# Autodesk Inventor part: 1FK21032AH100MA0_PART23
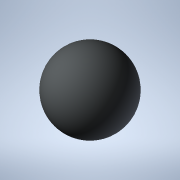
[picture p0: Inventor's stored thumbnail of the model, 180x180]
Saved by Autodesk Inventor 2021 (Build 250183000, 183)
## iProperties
Created: 2025-04
Part Number: 1FK21032AH100MA0_PART23
Material: Generic
Catalog Web Link: www.3dfindit.com
Description: -Servo synchronous motor
Document SubType Name: Modeling
Designer: psAdmin
Mass: 0.113097 g
Surface Area: 1.13097 cm^2
Volume: 0.113097 cm^3
Density: 1 g/cm^3
Appearance: PSOLRGB-212-217-219
Category: PARTsolutions
Title: 1FK21032AH100MA0_PART23
Author: Cadenas PARTsolutions
Comments: Servo synchronous motor
Sending System: PARTsolutions
Preprocessor: ST-DEVELOPER v19.3
PSOL_IDENT_0: {$CADENAS_DATA/23d-libs/siemens_ag/_cat_/12/33/1fk21032ah100ma0.prj},216 {VTYP=3D},{NB=1FK21032AH100
PSOL_IDENT_1: MA0_PART23},{LINA=1FK21032AH100MA0_PART23},{NN=1FK21032AH100MA0_PART23},{NOPRJ=TRUE},{DATE=19.08.202
PSOL_IDENT_2: 5 14:00:27},{GEOMDATE=30.07.2025 02:02:58},{VERSION=},{LINEID=10},{WBVAR=},{WBNUMERIC=}  {NB=1FK2103
PSOL_IDENT_3: 2AH100MA0_PART23},{LINA=1FK21032AH100MA0_PART23},{KT=DUMMY},{PREVIEW=../../../_pool_/d3/78/p_d211_xx
PSOL_IDENT_4: _00934j.png},{DESCSHORT=SIMOTICS S-1FK2 HD, SINAMICS S210 3AC 400V-480V, 0.59 Nm, 4500 rpm},{DESCLON
PSOL_IDENT_5: G=SIMOTICS S-1FK2 HD servo motor M0=0.64 Nm; PN = 0.28 kW at nN=4500 rpm (380-480 V); PN = 0.167 kW
PSOL_IDENT_6: at nN=2500 rpm (200-240 V); with holding brake; degree of protection IP64; cylindrical shaft D14 x 3
PSOL_IDENT_7: 0 mm; absolute encoder 22-bit + 12-bit multiturn (encoder AM22DQC); with OCC interface; plug size M1
PSOL_IDENT_8: 7, rotatable; SIMOTICS S-1FK2 servomotorfor a wide range of uses in industrial environments. SIMOTIC
PSOL_IDENT_9: S S‑1FK2 servomotors are compact synchronous motors with a high dynamic performance that set themsel
PSOL_IDENT_10: ves apart as a result of their high power density, degree of protection and overload capability. The
PSOL_IDENT_11: motors are available in two variants: as High Dynamic variant (highest dynamic performance as a res
PSOL_IDENT_12: ult of the low intrinsic moment of inertia for applications demanding a high dynamic performance wit
PSOL_IDENT_13: h low moved masses) - and as Compact variant (precise and stable closed-loop control for medium up t
PSOL_IDENT_14: o large moved masses as a result of a medium intrinsic moment of inertia). SIMOTICSS‑1FK2 servomotor
PSOL_IDENT_15: s fully exploit their strengths in a system with the SINAMICSS210 frequency converter and simple con
PSOL_IDENT_16: nection using the one cable connection (OCC). Advantages include the short control and positioning t
PSOL_IDENT_17: imes, fast and precise correction of disturbing quantities as well as stable control with a high dyn
PSOL_IDENT_18: amic performance. The servo motors can be configured to address a wide range of requirements. For ex
PSOL_IDENT_19: ample with and without holding brake, IP64 or IP65 degree of protection, singleturn or multiturn abs
PSOL_IDENT_20: olute encoders - to name just a few. Further, the servomotors are available in different shaft heigh
PSOL_IDENT_21: ts extending from 20 to 100. A shaft sealing ring is available to achieve an IP65 degree of protecti
PSOL_IDENT_22: on and for subsequent mounting at the motor or as spare part. SIMOTICS - the optimum motor for each
PSOL_IDENT_23: and every motion control application.},{INTNO=195125315563},{SUPPLIERALTNO=1FK2103-2AH10-0MA0},{MANU
PSOL_IDENT_24: ID=1FK21032AH100MA0},{MANUNAME=Siemens},{MANUTYPEDESC=SYNCHRONOUS MOTOR 1FK2 HD 0,64 NM},{AAU732=SIM
PSOL_IDENT_25: OTICS},{AAO057=S-1FK2},{AAU734=SIMOTICS S-1FK2 HD servo motor M0=0.64 Nm; PN = 0.28 kW at nN=4500 rp
PSOL_IDENT_26: m (380-480 V); PN = 0.167 kW at nN=2500 rpm (200-240 V); with holding brake; degree of protection IP
PSOL_IDENT_27: 64; cylindrical shaft D14 x 30 mm; absolute encoder 22-bit + 12-bit multiturn (encoder AM22DQC); wit
PSOL_IDENT_28: h OCC interface; plug size M17, rotatable;},{AAW338=SYNCHRONOUS MOTOR 1FK2 HD 0,64 NM},{AAO742=SIMOT
PSOL_IDENT_29: ICS},{AAO663=4034106444723},{NOCUPEROU=1},{PRICEQUANTITY=1},{QUANTITYMIN=1},{QUANTITYINT=1},{CTN=850
PSOL_IDENT_30: 15100},{COO=RO},{AAO676=1FK2103-2AH10-0MA0},{AAO677=Siemens AG},{ORDERUNIT=C62},{CONTENTUNIT=C62}
NB: 1FK21032AH100MA0_PART23
NT: Servo synchronous motor
NBSYN: $MANUID._PART23
LINA: 1FK21032AH100MA0_PART23
CATALOG: SIEMENS
PREVIEW: ../../../_pool_/d3/78/p_d211_xx_00934j.png
DESCSHORT: SIMOTICS S-1FK2 HD, SINAMICS S210 3AC 400V-480V, 0.59 Nm, 4500 rpm
DESCLONG: SIMOTICS S-1FK2 HD servo motor M0=0.64 Nm; PN = 0.28 kW at nN=4500 rpm (380-480 V); PN = 0.167 kW at nN=2500 rpm (200-240 V); with holding brake; degree of prot
INTNO: 195125315563
SUPPLIERALTNO: 1FK2103-2AH10-0MA0
MANUID: 1FK21032AH100MA0
MANUNAME: Siemens
MANUTYPEDESC: SYNCHRONOUS MOTOR 1FK2 HD 0,64 NM
AAU732: SIMOTICS
AAO057: S-1FK2
AAU734: SIMOTICS S-1FK2 HD servo motor M0=0.64 Nm; PN = 0.28 kW at nN=4500 rpm (380-480 V); PN = 0.167 kW at nN=2500 rpm (200-240 V); with holding brake; degree of prot
AAW338: SYNCHRONOUS MOTOR 1FK2 HD 0,64 NM
AAO742: SIMOTICS
AAO663: 4034106444723.0
NOCUPEROU: 1
PRICEQUANTITY: 1
QUANTITYMIN: 1
QUANTITYINT: 1
CTN: 85015100
COO: RO
ARTICLENO: 1FK21032AH100MA0_PART23
BOMINFO: 1FK21032AH100MA0_PART23
CREATOR: CADENAS GmbH
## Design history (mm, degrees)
feature "2025_04_17_15_06_16_0705"
body "Solid1"
